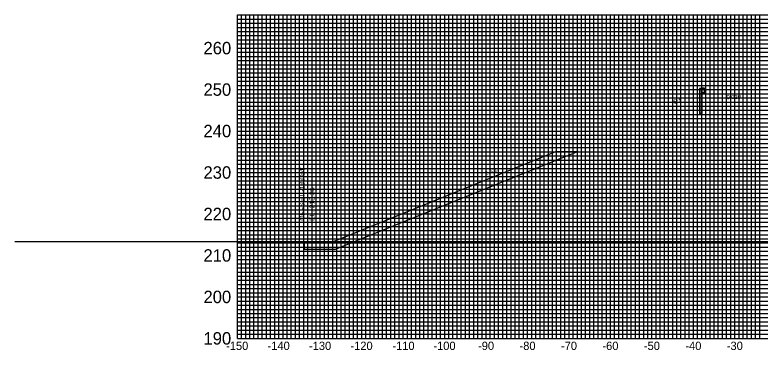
# Model space of a CAD drawing. Extents: x -204 to 158, y 187 to 272.
# Drawn here: x -203.7 to -23.9, y 187.2 to 268 of the extents above; entities that cross this region are included whole.
import ezdxf

# ---------------------------------------------------------------- set-up
doc = ezdxf.new("R2010")
doc.units = 0
for name, color, linetype in [('Default', 7, 'Continuous'), ('DESIGN - CENTERLINE - Proposed', 7, 'Continuous'), ('DESIGN - TRANSPORTATION - Driveway Shading', 7, 'Continuous'), ('SURVEY - CONTOURS - Index with Text', 7, 'Continuous'), ('SURVEY - TRANSPORTATION - Roads', 7, 'Continuous'), ('SURVEY - TRANSPORTATION - Roads Text', 7, 'Continuous')]:
    doc.layers.add(name, color=color, linetype=linetype)

msp = doc.modelspace()

# ---------------------------------------------------------------- linework, layer by layer
at = {"layer": 'Default'}
msp.add_lwpolyline([(-133.84, 213.4), (-126.84, 213.4), (-73.17, 235.04), (-67.82, 235.04), (-126.45, 211.4), (-133.84, 211.4)], close=True, dxfattribs=at)
at = {"layer": 'DESIGN - CENTERLINE - Proposed'}
for p, q in [((-38.48, 250.26), (-38.5, 250.26)), ((-38.5, 250.26), (-38.5, 250.26)), ((-38.5, 250.26), (-38.48, 250.26)), ((-38.5, 250.26), (-38.5, 244.26)), ((-38.5, 250.26), (-38.5, 244.26)), ((-38.03, 250.26), (-38.48, 250.26)), ((-38.48, 250.26), (-38.48, 250.26)), ((-38.48, 250.26), (-38.48, 250.26)), ((-38.48, 250.26), (-38.03, 250.26)), ((-38.48, 250.26), (-38.48, 244.26)), ((-38.48, 250.26), (-38.48, 244.26)), ((-38.48, 250.26), (-38.48, 244.26)), ((-38.48, 250.26), (-38.48, 244.26)), ((-38.01, 250.26), (-38.03, 250.26)), ((-38.03, 250.26), (-38.03, 250.26)), ((-38.03, 250.26), (-38.03, 250.26)), ((-38.03, 250.26), (-38.01, 250.26)), ((-38.03, 250.26), (-38.03, 244.26)), ((-38.03, 250.26), (-38.03, 244.26)), ((-38.03, 250.26), (-38.03, 244.26)), ((-38.03, 250.26), (-38.03, 244.26)), ((-37.39, 250.36), (-38.01, 250.36)), ((-38.01, 250.36), (-38.01, 250.36)), ((-38.01, 250.36), (-37.39, 250.36)), ((-38.01, 250.36), (-38.01, 249.19)), ((-38.01, 250.36), (-38.01, 249.19)), ((-38.01, 250.26), (-38.01, 250.26)), ((-38.01, 250.26), (-38.01, 244.26)), ((-38.01, 250.26), (-38.01, 244.26)), ((-37.39, 250.36), (-37.39, 250.36)), ((-37.39, 250.36), (-37.39, 249.19)), ((-37.39, 250.36), (-37.39, 249.19)), ((-37.38, 250.27), (-37.34, 250.27)), ((-37.13, 250.02), (-37.34, 249.87)), ((-37.24, 250.23), (-37.13, 250.15)), ((-37.39, 249.19), (-38.01, 249.19)), ((-38.01, 249.19), (-38.01, 249.19)), ((-38.01, 249.19), (-37.39, 249.19)), ((-37.39, 249.19), (-37.39, 249.19)), ((-37.38, 249.81), (-37.38, 249.72)), ((-37.34, 249.26), (-37.38, 249.25)), ((-37.34, 249.65), (-37.13, 249.51)), ((-37.13, 249.38), (-37.24, 249.3)), ((-38.48, 244.26), (-38.5, 244.26)), ((-38.5, 244.26), (-38.5, 244.26)), ((-38.5, 244.26), (-38.48, 244.26)), ((-38.03, 244.26), (-38.48, 244.26)), ((-38.48, 244.26), (-38.48, 244.26)), ((-38.48, 244.26), (-38.48, 244.26)), ((-38.48, 244.26), (-38.03, 244.26)), ((-38.01, 244.26), (-38.03, 244.26)), ((-38.03, 244.26), (-38.03, 244.26)), ((-38.03, 244.26), (-38.03, 244.26)), ((-38.03, 244.26), (-38.01, 244.26)), ((-38.01, 244.26), (-38.01, 244.26))]:
    msp.add_line(p, q, dxfattribs=at)
for centre, radius, start, end in [((-37.3, 249.81), 0.0781, 125, 180), ((-37.39, 250.02), 0.25, 55, 80), ((-37.18, 250.09), 0.0781, 305, 55), ((-37.3, 249.72), 0.0781, 180, 235), ((-37.39, 249.5), 0.25, 280, 305), ((-37.18, 249.44), 0.0781, 305, 55)]:
    msp.add_arc(centre, radius, start, end, dxfattribs=at)
at = {"layer": 'SURVEY - CONTOURS - Index with Text'}
for p, q in [((-150, 268.01), (150, 268.01)), ((-150, 190), (-150, 268.01)), ((-150, 268.01), (150, 268.01)), ((-150, 190), (-150, 268.01)), ((-140, 190), (-140, 268.01)), ((-140, 190), (-140, 268.01)), ((-130, 190), (-130, 268.01)), ((-130, 190), (-130, 268.01)), ((-120, 190), (-120, 268.01)), ((-120, 190), (-120, 268.01)), ((-110, 190), (-110, 268.01)), ((-110, 190), (-110, 268.01)), ((-100, 190), (-100, 268.01)), ((-100, 190), (-100, 268.01)), ((-90, 190), (-90, 268.01)), ((-90, 190), (-90, 268.01)), ((-80, 190), (-80, 268.01)), ((-80, 190), (-80, 268.01)), ((-70, 190), (-70, 268.01)), ((-70, 190), (-70, 268.01)), ((-60, 190), (-60, 268.01)), ((-60, 190), (-60, 268.01)), ((-50, 190), (-50, 268.01)), ((-50, 190), (-50, 268.01)), ((-40, 190), (-40, 268.01)), ((-40, 190), (-40, 268.01)), ((-30, 190), (-30, 268.01)), ((-30, 190), (-30, 268.01)), ((-150, 260), (150, 260)), ((-150, 260), (150, 260)), ((-150, 250), (150, 250)), ((-150, 250), (150, 250)), ((-150, 240), (150, 240)), ((-150, 240), (150, 240)), ((-150, 230), (150, 230)), ((-150, 230), (150, 230)), ((-150, 220), (150, 220)), ((-150, 220), (150, 220)), ((-150, 210), (150, 210)), ((-150, 210), (150, 210)), ((-150, 200), (150, 200)), ((-150, 200), (150, 200)), ((-150, 190), (150, 190)), ((-150, 190), (150, 190))]:
    msp.add_line(p, q, dxfattribs=at)
at = {"layer": 'SURVEY - TRANSPORTATION - Roads'}
for p, q in [((-150, 268), (150, 268)), ((-150, 268), (150, 268)), ((-149, 190), (-149, 268.01)), ((-149, 190), (-149, 268.01)), ((-148, 190), (-148, 268.01)), ((-148, 190), (-148, 268.01)), ((-147, 190), (-147, 268.01)), ((-147, 190), (-147, 268.01)), ((-146, 190), (-146, 268.01)), ((-146, 190), (-146, 268.01)), ((-145, 190), (-145, 268.01)), ((-145, 190), (-145, 268.01)), ((-144, 190), (-144, 268.01)), ((-144, 190), (-144, 268.01)), ((-143, 190), (-143, 268.01)), ((-143, 190), (-143, 268.01)), ((-142, 190), (-142, 268.01)), ((-142, 190), (-142, 268.01)), ((-141, 190), (-141, 268.01)), ((-141, 190), (-141, 268.01)), ((-139, 190), (-139, 268.01)), ((-139, 190), (-139, 268.01)), ((-138, 190), (-138, 268.01)), ((-138, 190), (-138, 268.01)), ((-137, 190), (-137, 268.01)), ((-137, 190), (-137, 268.01)), ((-136, 190), (-136, 268.01)), ((-136, 190), (-136, 268.01)), ((-135, 190), (-135, 268.01)), ((-135, 190), (-135, 268.01)), ((-134, 190), (-134, 268.01)), ((-134, 190), (-134, 268.01)), ((-133, 190), (-133, 268.01)), ((-133, 190), (-133, 268.01)), ((-132, 190), (-132, 268.01)), ((-132, 190), (-132, 268.01)), ((-131, 190), (-131, 268.01)), ((-131, 190), (-131, 268.01)), ((-129, 190), (-129, 268.01)), ((-129, 190), (-129, 268.01)), ((-128, 190), (-128, 268.01)), ((-128, 190), (-128, 268.01)), ((-127, 190), (-127, 268.01)), ((-127, 190), (-127, 268.01)), ((-126, 190), (-126, 268.01)), ((-126, 190), (-126, 268.01)), ((-125, 190), (-125, 268.01)), ((-125, 190), (-125, 268.01)), ((-124, 190), (-124, 268.01)), ((-124, 190), (-124, 268.01)), ((-123, 190), (-123, 268.01)), ((-123, 190), (-123, 268.01)), ((-122, 190), (-122, 268.01)), ((-122, 190), (-122, 268.01)), ((-121, 190), (-121, 268.01)), ((-121, 190), (-121, 268.01)), ((-119, 190), (-119, 268.01)), ((-119, 190), (-119, 268.01)), ((-118, 190), (-118, 268.01)), ((-118, 190), (-118, 268.01)), ((-117, 190), (-117, 268.01)), ((-117, 190), (-117, 268.01)), ((-116, 190), (-116, 268.01)), ((-116, 190), (-116, 268.01)), ((-115, 190), (-115, 268.01)), ((-115, 190), (-115, 268.01)), ((-114, 190), (-114, 268.01)), ((-114, 190), (-114, 268.01)), ((-113, 190), (-113, 268.01)), ((-113, 190), (-113, 268.01)), ((-112, 190), (-112, 268.01)), ((-112, 190), (-112, 268.01)), ((-111, 190), (-111, 268.01)), ((-111, 190), (-111, 268.01)), ((-109, 190), (-109, 268.01)), ((-109, 190), (-109, 268.01)), ((-108, 190), (-108, 268.01)), ((-108, 190), (-108, 268.01)), ((-107, 190), (-107, 268.01)), ((-107, 190), (-107, 268.01)), ((-106, 190), (-106, 268.01)), ((-106, 190), (-106, 268.01)), ((-105, 190), (-105, 268.01)), ((-105, 190), (-105, 268.01)), ((-104, 190), (-104, 268.01)), ((-104, 190), (-104, 268.01)), ((-103, 190), (-103, 268.01)), ((-103, 190), (-103, 268.01)), ((-102, 190), (-102, 268.01)), ((-102, 190), (-102, 268.01)), ((-101, 190), (-101, 268.01)), ((-101, 190), (-101, 268.01)), ((-99, 190), (-99, 268.01)), ((-99, 190), (-99, 268.01)), ((-98, 190), (-98, 268.01)), ((-98, 190), (-98, 268.01)), ((-97, 190), (-97, 268.01)), ((-97, 190), (-97, 268.01)), ((-96, 190), (-96, 268.01)), ((-96, 190), (-96, 268.01)), ((-95, 190), (-95, 268.01)), ((-95, 190), (-95, 268.01)), ((-94, 190), (-94, 268.01)), ((-94, 190), (-94, 268.01)), ((-93, 190), (-93, 268.01)), ((-93, 190), (-93, 268.01)), ((-92, 190), (-92, 268.01)), ((-92, 190), (-92, 268.01)), ((-91, 190), (-91, 268.01)), ((-91, 190), (-91, 268.01)), ((-89, 190), (-89, 268.01)), ((-89, 190), (-89, 268.01)), ((-88, 190), (-88, 268.01)), ((-88, 190), (-88, 268.01)), ((-87, 190), (-87, 268.01)), ((-87, 190), (-87, 268.01)), ((-86, 190), (-86, 268.01)), ((-86, 190), (-86, 268.01)), ((-85, 190), (-85, 268.01)), ((-85, 190), (-85, 268.01)), ((-84, 190), (-84, 268.01)), ((-84, 190), (-84, 268.01)), ((-83, 190), (-83, 268.01)), ((-83, 190), (-83, 268.01)), ((-82, 190), (-82, 268.01)), ((-82, 190), (-82, 268.01)), ((-81, 190), (-81, 268.01)), ((-81, 190), (-81, 268.01)), ((-79, 190), (-79, 268.01)), ((-79, 190), (-79, 268.01)), ((-78, 190), (-78, 268.01)), ((-78, 190), (-78, 268.01)), ((-77, 190), (-77, 268.01)), ((-77, 190), (-77, 268.01)), ((-76, 190), (-76, 268.01)), ((-76, 190), (-76, 268.01)), ((-75, 190), (-75, 268.01)), ((-75, 190), (-75, 268.01)), ((-74, 190), (-74, 268.01)), ((-74, 190), (-74, 268.01)), ((-73, 190), (-73, 268.01)), ((-73, 190), (-73, 268.01)), ((-72, 190), (-72, 268.01)), ((-72, 190), (-72, 268.01)), ((-71, 190), (-71, 268.01)), ((-71, 190), (-71, 268.01)), ((-69, 190), (-69, 268.01)), ((-69, 190), (-69, 268.01)), ((-68, 190), (-68, 268.01)), ((-68, 190), (-68, 268.01)), ((-67, 190), (-67, 268.01)), ((-67, 190), (-67, 268.01)), ((-66, 190), (-66, 268.01)), ((-66, 190), (-66, 268.01)), ((-65, 190), (-65, 268.01)), ((-65, 190), (-65, 268.01)), ((-64, 190), (-64, 268.01)), ((-64, 190), (-64, 268.01)), ((-63, 190), (-63, 268.01)), ((-63, 190), (-63, 268.01)), ((-62, 190), (-62, 268.01)), ((-62, 190), (-62, 268.01)), ((-61, 190), (-61, 268.01)), ((-61, 190), (-61, 268.01)), ((-59, 190), (-59, 268.01)), ((-59, 190), (-59, 268.01)), ((-58, 190), (-58, 268.01)), ((-58, 190), (-58, 268.01)), ((-57, 190), (-57, 268.01)), ((-57, 190), (-57, 268.01)), ((-56, 190), (-56, 268.01)), ((-56, 190), (-56, 268.01)), ((-55, 190), (-55, 268.01)), ((-55, 190), (-55, 268.01)), ((-54, 190), (-54, 268.01)), ((-54, 190), (-54, 268.01)), ((-53, 190), (-53, 268.01)), ((-53, 190), (-53, 268.01)), ((-52, 190), (-52, 268.01)), ((-52, 190), (-52, 268.01)), ((-51, 190), (-51, 268.01)), ((-51, 190), (-51, 268.01)), ((-49, 190), (-49, 268.01)), ((-49, 190), (-49, 268.01)), ((-48, 190), (-48, 268.01)), ((-48, 190), (-48, 268.01)), ((-47, 190), (-47, 268.01)), ((-47, 190), (-47, 268.01)), ((-46, 190), (-46, 268.01)), ((-46, 190), (-46, 268.01)), ((-45, 190), (-45, 268.01)), ((-45, 190), (-45, 268.01)), ((-44, 190), (-44, 268.01)), ((-44, 190), (-44, 268.01)), ((-43, 190), (-43, 268.01)), ((-43, 190), (-43, 268.01)), ((-42, 190), (-42, 268.01)), ((-42, 190), (-42, 268.01)), ((-41, 190), (-41, 268.01)), ((-41, 190), (-41, 268.01)), ((-39, 190), (-39, 268.01)), ((-39, 190), (-39, 268.01)), ((-38, 190), (-38, 268.01)), ((-38, 190), (-38, 268.01)), ((-37, 190), (-37, 268.01)), ((-37, 190), (-37, 268.01)), ((-36, 190), (-36, 268.01)), ((-36, 190), (-36, 268.01)), ((-35, 190), (-35, 268.01)), ((-35, 190), (-35, 268.01)), ((-34, 190), (-34, 268.01)), ((-34, 190), (-34, 268.01)), ((-33, 190), (-33, 268.01)), ((-33, 190), (-33, 268.01)), ((-32, 190), (-32, 268.01)), ((-32, 190), (-32, 268.01)), ((-31, 190), (-31, 268.01)), ((-31, 190), (-31, 268.01)), ((-29, 190), (-29, 268.01)), ((-29, 190), (-29, 268.01)), ((-28, 190), (-28, 268.01)), ((-28, 190), (-28, 268.01)), ((-27, 190), (-27, 268.01)), ((-27, 190), (-27, 268.01)), ((-26, 190), (-26, 268.01)), ((-26, 190), (-26, 268.01)), ((-25, 190), (-25, 268.01)), ((-25, 190), (-25, 268.01)), ((-24, 190), (-24, 268.01)), ((-24, 190), (-24, 268.01)), ((-150, 267), (150, 267)), ((-150, 267), (150, 267)), ((-150, 266), (150, 266)), ((-150, 266), (150, 266)), ((-150, 265), (150, 265)), ((-150, 265), (150, 265)), ((-150, 264), (150, 264)), ((-150, 264), (150, 264)), ((-150, 263), (150, 263)), ((-150, 263), (150, 263)), ((-150, 262), (150, 262)), ((-150, 262), (150, 262)), ((-150, 261), (150, 261)), ((-150, 261), (150, 261)), ((-150, 259), (150, 259)), ((-150, 259), (150, 259)), ((-150, 258), (150, 258)), ((-150, 258), (150, 258)), ((-150, 257), (150, 257)), ((-150, 257), (150, 257)), ((-150, 256), (150, 256)), ((-150, 256), (150, 256)), ((-150, 255), (150, 255)), ((-150, 255), (150, 255)), ((-150, 254), (150, 254)), ((-150, 254), (150, 254)), ((-150, 253), (150, 253)), ((-150, 253), (150, 253)), ((-150, 252), (150, 252)), ((-150, 252), (150, 252)), ((-150, 251), (150, 251)), ((-150, 251), (150, 251)), ((-150, 249), (150, 249)), ((-150, 249), (150, 249)), ((-150, 248), (150, 248)), ((-150, 248), (150, 248)), ((-150, 247), (150, 247)), ((-150, 247), (150, 247)), ((-150, 246), (150, 246)), ((-150, 246), (150, 246)), ((-150, 245), (150, 245)), ((-150, 245), (150, 245)), ((-150, 244), (150, 244)), ((-150, 244), (150, 244)), ((-150, 243), (150, 243)), ((-150, 243), (150, 243)), ((-150, 242), (150, 242)), ((-150, 242), (150, 242)), ((-150, 241), (150, 241)), ((-150, 241), (150, 241)), ((-150, 239), (150, 239)), ((-150, 239), (150, 239)), ((-150, 238), (150, 238)), ((-150, 238), (150, 238)), ((-150, 237), (150, 237)), ((-150, 237), (150, 237)), ((-150, 236), (150, 236)), ((-150, 236), (150, 236)), ((-150, 235), (150, 235)), ((-150, 234), (150, 234)), ((-150, 234), (150, 234)), ((-150, 233), (150, 233)), ((-150, 233), (150, 233)), ((-150, 232), (150, 232)), ((-150, 232), (150, 232)), ((-150, 231), (150, 231)), ((-150, 231), (150, 231)), ((-150, 229), (150, 229)), ((-150, 229), (150, 229)), ((-150, 228), (150, 228)), ((-150, 228), (150, 228)), ((-150, 227), (150, 227)), ((-150, 227), (150, 227)), ((-150, 226), (150, 226)), ((-150, 226), (150, 226)), ((-150, 225), (150, 225)), ((-150, 225), (150, 225)), ((-150, 224), (150, 224)), ((-150, 224), (150, 224)), ((-150, 223), (150, 223)), ((-150, 223), (150, 223)), ((-150, 222), (150, 222)), ((-150, 222), (150, 222)), ((-150, 221), (150, 221)), ((-150, 221), (150, 221)), ((-150, 219), (150, 219)), ((-150, 219), (150, 219)), ((-150, 218), (150, 218)), ((-150, 218), (150, 218)), ((-150, 217), (150, 217)), ((-150, 217), (150, 217)), ((-150, 216), (150, 216)), ((-150, 216), (150, 216)), ((-150, 215), (150, 215)), ((-150, 215), (150, 215)), ((-150, 214), (150, 214)), ((-150, 214), (150, 214)), ((-203.67, 213.36), (96.33, 213.36)), ((-150, 213), (150, 213)), ((-150, 213), (150, 213)), ((-150, 212), (150, 212)), ((-150, 212), (150, 212)), ((-150, 211), (150, 211)), ((-150, 211), (150, 211)), ((-150, 209), (150, 209)), ((-150, 209), (150, 209)), ((-150, 208), (150, 208)), ((-150, 208), (150, 208)), ((-150, 207), (150, 207)), ((-150, 207), (150, 207)), ((-150, 206), (150, 206)), ((-150, 206), (150, 206)), ((-150, 205), (150, 205)), ((-150, 205), (150, 205)), ((-150, 204), (150, 204)), ((-150, 204), (150, 204)), ((-150, 203), (150, 203)), ((-150, 203), (150, 203)), ((-150, 202), (150, 202)), ((-150, 202), (150, 202)), ((-150, 201), (150, 201)), ((-150, 201), (150, 201)), ((-150, 199), (150, 199)), ((-150, 199), (150, 199)), ((-150, 198), (150, 198)), ((-150, 198), (150, 198)), ((-150, 197), (150, 197)), ((-150, 197), (150, 197)), ((-150, 196), (150, 196)), ((-150, 196), (150, 196)), ((-150, 195), (150, 195)), ((-150, 195), (150, 195)), ((-150, 194), (150, 194)), ((-150, 194), (150, 194)), ((-150, 193), (150, 193)), ((-150, 193), (150, 193)), ((-150, 192), (150, 192)), ((-150, 192), (150, 192)), ((-150, 191), (150, 191)), ((-150, 191), (150, 191))]:
    msp.add_line(p, q, dxfattribs=at)

# ---------------------------------------------------------------- texts
at = {"layer": 'DESIGN - TRANSPORTATION - Driveway Shading'}
for s, height, rotation, p in [('-0.020', 1, 1.1458, (-32.45, 247.66)), ('-0.020', 1, 1.1458, (-32.45, 247.66)), ('6:1', 1, 9.4623, (-44.73, 246.57)), ('6:1', 1, 9.4623, (-44.73, 246.57)), ("OFFSET -133.84'", 1.2, 90, (-133.81, 218.36)), ('2.5:1', 1, 21.9582, (-90.09, 229.24)), ('213.36', 1.2, 90, (-131.41, 221.34)), ('EL. ', 1.2, 90, (-131.41, 218.36))]:
    msp.add_text(s, height=height, rotation=rotation, dxfattribs=at).set_placement(p)
at = {"layer": 'SURVEY - TRANSPORTATION - Roads Text'}
for s, height, p in [('260', 3, (-158.19, 258.5)), ('260', 3, (-158.19, 258.5)), ('250', 3, (-158.19, 248.5)), ('250', 3, (-158.19, 248.5)), ('240', 3, (-158.19, 238.5)), ('240', 3, (-158.19, 238.5)), ('230', 3, (-158.19, 228.5)), ('230', 3, (-158.19, 228.5)), ('220', 3, (-158.19, 218.5)), ('220', 3, (-158.19, 218.5)), ('210', 3, (-158.19, 208.5)), ('210', 3, (-158.19, 208.5)), ('200', 3, (-158.19, 198.5)), ('200', 3, (-158.19, 198.5)), ('190', 3, (-158.19, 188.5)), ('190', 3, (-158.19, 188.5)), ('-150', 2, (-152.73, 187.2)), ('-150', 2, (-152.73, 187.2)), ('-140', 2, (-142.73, 187.2)), ('-140', 2, (-142.73, 187.2)), ('-130', 2, (-132.73, 187.2)), ('-130', 2, (-132.73, 187.2)), ('-120', 2, (-122.73, 187.2)), ('-120', 2, (-122.73, 187.2)), ('-110', 2, (-112.62, 187.2)), ('-110', 2, (-112.62, 187.2)), ('-100', 2, (-102.73, 187.2)), ('-100', 2, (-102.73, 187.2)), ('-90', 2, (-91.95, 187.2)), ('-90', 2, (-91.95, 187.2)), ('-80', 2, (-81.95, 187.2)), ('-80', 2, (-81.95, 187.2)), ('-70', 2, (-71.95, 187.2)), ('-70', 2, (-71.95, 187.2)), ('-60', 2, (-61.95, 187.2)), ('-60', 2, (-61.95, 187.2)), ('-50', 2, (-51.95, 187.2)), ('-50', 2, (-51.95, 187.2)), ('-40', 2, (-41.95, 187.2)), ('-40', 2, (-41.95, 187.2)), ('-30', 2, (-31.95, 187.2)), ('-30', 2, (-31.95, 187.2))]:
    msp.add_text(s, height=height, dxfattribs=at).set_placement(p)

doc.saveas('drawing.dxf')
